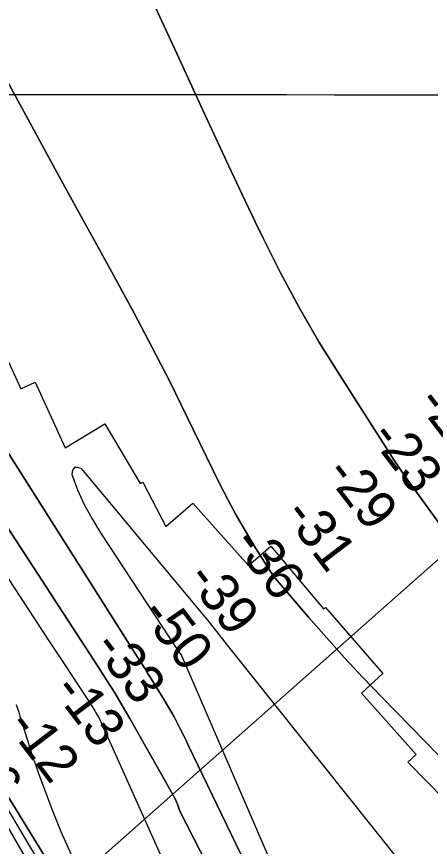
# Model space of a CAD drawing. Extents: x 3263578 to 3301413, y 764927 to 798602.
# Drawn here: x 3277420 to 3278134, y 786654 to 788086 of the extents above; entities that cross this region are included whole.
import ezdxf

# ---------------------------------------------------------------- set-up
doc = ezdxf.new("R2010")
doc.units = 0
for name, color, linetype in [('V-GRID-MAJR', 7, 'Continuous'), ('V-RIVR-RANG', 7, 'Continuous'), ('V-RRAP-RVMT', 7, 'Continuous'), ('V-TOPO-DPTH', 7, 'Continuous'), ('V-TOPO-MAJR', 7, 'Continuous'), ('V-TOPO-MINR', 7, 'Continuous'), ('V-TOPO-WATR', 7, 'Continuous')]:
    doc.layers.add(name, color=color, linetype=linetype)

msp = doc.modelspace()

# ---------------------------------------------------------------- linework, layer by layer
at = {"layer": 'V-GRID-MAJR'}
msp.add_spline([(3267732.7, 787953.5), (3270352.8, 787952.6), (3275593.1, 787951.5), (3280833.3, 787951.1), (3286073.6, 787951.5), (3291313.9, 787952.6), (3296554.1, 787954.5), (3299174.3, 787955.8)], degree=3, dxfattribs=at)
at = {"layer": 'V-RIVR-RANG'}
msp.add_line((3277254.1, 786359.2), (3278147.4, 787150), dxfattribs=at)
at = {"layer": 'V-RRAP-RVMT'}
for points in [[(3277050.8, 788201.5), (3277092.3, 788067.5), (3277100.3, 788070.3), (3277145.8, 787939.5), (3277153.8, 787942.5), (3277203.6, 787813.6), (3277212, 787817.1), (3277268.9, 787682.6), (3277302.2, 787696.7), (3277355.5, 787571), (3277366.6, 787576), (3277427.3, 787443.4), (3277452.4, 787454.9), (3277504, 787341.9)], [(3277504, 787341.9), (3277572.5, 787383.3), (3277633, 787280.3), (3277637.7, 787282.8), (3277677.4, 787206), (3277723.8, 787246.4), (3277819.9, 787138.6), (3277858.7, 787172.1), (3277949.5, 787063.9), (3277952.5, 787066.3), (3278051.7, 786952.4), (3278014.9, 786918.5), (3278108.9, 786812.7), (3278094.4, 786799.8), (3278190.5, 786701.7)]]:
    msp.add_lwpolyline(points, dxfattribs=at)
at = {"layer": 'V-TOPO-DPTH'}
for points in [[(3276856.5, 788146.6), (3276909.9, 787892.1), (3276910.3, 787890.2), (3276910.8, 787888.4), (3276911.4, 787886.6), (3276912.1, 787884.8), (3276912.9, 787883.1), (3276913.7, 787881.3), (3276914.7, 787879.7), (3276915.7, 787878), (3277398.4, 787128), (3277424.1, 787088.2), (3277449.9, 787048.4), (3277475.9, 787008.7), (3277502, 786969), (3277551.8, 786893.6), (3277553, 786891.7), (3277554.2, 786889.8), (3277555.4, 786887.9), (3277556.5, 786885.9), (3277563.1, 786874.5), (3278015.9, 785863.7)], [(3276856.5, 788146.6), (3276909.9, 787892.1), (3276910.3, 787890.2), (3276910.8, 787888.4), (3276911.4, 787886.6), (3276912.1, 787884.8), (3276912.9, 787883.1), (3276913.7, 787881.3), (3276914.7, 787879.7), (3276915.7, 787878), (3277398.4, 787128), (3277424.1, 787088.2), (3277449.9, 787048.4), (3277475.9, 787008.7), (3277502, 786969), (3277551.8, 786893.6), (3277553, 786891.7), (3277554.2, 786889.8), (3277555.4, 786887.9), (3277556.5, 786885.9), (3277563.1, 786874.5), (3278015.9, 785863.7)], [(3277651.6, 788119.4), (3277673.9, 788070.7), (3277696.2, 788022.1), (3277718.6, 787973.4), (3277741, 787924.7), (3277763.5, 787876.2), (3277786.2, 787827.6), (3277809.1, 787779.2), (3277832.1, 787730.9), (3277844.7, 787704.6), (3277875.3, 787643.8), (3277907.3, 787583.8), (3277941.5, 787525), (3277977.2, 787467), (3278071.9, 787319.3), (3278078.9, 787308.6), (3278086, 787298), (3278093.3, 787287.6), (3278100.7, 787277.2), (3278323.2, 786970.6)], [(3277651.6, 788119.4), (3277673.9, 788070.7), (3277696.2, 788022.1), (3277718.6, 787973.4), (3277741, 787924.7), (3277763.5, 787876.2), (3277786.2, 787827.6), (3277809.1, 787779.2), (3277832.1, 787730.9), (3277844.7, 787704.6), (3277875.3, 787643.8), (3277907.3, 787583.8), (3277941.5, 787525), (3277977.2, 787467), (3278071.9, 787319.3), (3278078.9, 787308.6), (3278086, 787298), (3278093.3, 787287.6), (3278100.7, 787277.2), (3278323.2, 786970.6)], [(3278565.3, 786383.6), (3278049.6, 786911.8), (3278017.3, 786945.5), (3277985.4, 786979.7), (3277954.3, 787014.5), (3277923.6, 787049.8), (3277869.3, 787113.2), (3277866.2, 787117.1), (3277863.1, 787121.1), (3277860.3, 787125.1), (3277857.5, 787129.3), (3277830, 787172.8), (3277814, 787199.1), (3277798.6, 787225.7), (3277784.1, 787252.7), (3277770.2, 787280.2), (3277714.5, 787394.9), (3277684.7, 787455.1), (3277654.2, 787515), (3277622.8, 787574.4), (3277590.8, 787633.5), (3277558.4, 787692.3), (3277526, 787751.2), (3277493.8, 787810.1), (3277461.6, 787869.1), (3277332.1, 788106.4)], [(3277332.1, 788106.4), (3277461.6, 787869.1), (3277493.8, 787810.1), (3277526, 787751.2), (3277558.4, 787692.3), (3277590.8, 787633.5), (3277622.8, 787574.4), (3277654.2, 787515), (3277684.7, 787455.1), (3277714.5, 787394.9), (3277770.2, 787280.2), (3277784.1, 787252.7), (3277798.6, 787225.7), (3277814, 787199.1), (3277830, 787172.8), (3277857.5, 787129.3), (3277860.3, 787125.1), (3277863.1, 787121.1), (3277866.2, 787117.1), (3277869.3, 787113.2), (3277923.6, 787049.8), (3277954.3, 787014.5), (3277985.4, 786979.7), (3278017.3, 786945.5), (3278049.6, 786911.8), (3278565.3, 786383.6)], [(3277116.8, 787789.3), (3277632.7, 786974.6), (3277637.1, 786967.5), (3277641.6, 786960.4), (3277646, 786953.2), (3277650.4, 786946.1), (3277674.4, 786907.3), (3277680.3, 786897.5), (3277686, 786887.6), (3277691.6, 786877.6), (3277696.9, 786867.5), (3277702.2, 786857.3), (3277707.3, 786847.1), (3277712.4, 786836.8), (3277717.4, 786826.5), (3277814.9, 786624)], [(3277814.9, 786624), (3277717.4, 786826.5), (3277712.4, 786836.8), (3277707.3, 786847.1), (3277702.2, 786857.3), (3277696.9, 786867.5), (3277691.6, 786877.6), (3277686, 786887.6), (3277680.3, 786897.5), (3277674.4, 786907.3), (3277650.4, 786946.1), (3277646, 786953.2), (3277641.6, 786960.4), (3277637.1, 786967.5), (3277632.7, 786974.6), (3277116.8, 787789.3)], [(3278079.8, 785976.6), (3277701.7, 786714.9), (3277697.4, 786726.9), (3277692.2, 786738.5), (3277615.2, 786875), (3277602.5, 786897.1), (3277589.4, 786918.9), (3277576, 786940.5), (3277562.3, 786962), (3277312.5, 787345.4)], [(3278079.8, 785976.6), (3277701.7, 786714.9), (3277697.4, 786726.9), (3277692.2, 786738.5), (3277615.2, 786875), (3277602.5, 786897.1), (3277589.4, 786918.9), (3277576, 786940.5), (3277562.3, 786962), (3277312.5, 787345.4)], [(3277259.6, 786938), (3277928.1, 785781.1)], [(3277259.6, 786938), (3277928.1, 785781.1)], [(3277967.8, 785823.8), (3277388.8, 786766.2)], [(3277967.8, 785823.8), (3277388.8, 786766.2)]]:
    msp.add_lwpolyline(points, dxfattribs=at)
at = {"layer": 'V-TOPO-MAJR'}
msp.add_lwpolyline([(3278071.7, 786640), (3277786.3, 786998.7), (3277769.4, 787019.8), (3277752.5, 787040.8), (3277735.4, 787061.6), (3277718.2, 787082.4), (3277532.7, 787305.4), (3277525.5, 787308.1), (3277519.9, 787307.8), (3277516.8, 787303.1), (3277515.3, 787295.6), (3277525.5, 787269.5), (3277537, 787244), (3277550.3, 787219.5), (3277564.8, 787195.5), (3277684.1, 787013.8), (3277689.1, 787006.2), (3277694.2, 786998.5), (3277699.3, 786990.9), (3277704.4, 786983.3), (3278016.2, 786261.8)], dxfattribs=at)
at = {"layer": 'V-TOPO-MINR'}
for points in [[(3276856.5, 788146.6), (3276909.9, 787892.1), (3276910.3, 787890.2), (3276910.8, 787888.4), (3276911.4, 787886.6), (3276912.1, 787884.8), (3276912.9, 787883.1), (3276913.7, 787881.3), (3276914.7, 787879.7), (3276915.7, 787878), (3277398.4, 787128), (3277424.1, 787088.2), (3277449.9, 787048.4), (3277475.9, 787008.7), (3277502, 786969), (3277551.8, 786893.6), (3277553, 786891.7), (3277554.2, 786889.8), (3277555.4, 786887.9), (3277556.5, 786885.9), (3277563.1, 786874.5), (3278015.9, 785863.7)], [(3278323.2, 786970.6), (3278100.7, 787277.2), (3278093.3, 787287.6), (3278086, 787298), (3278078.9, 787308.6), (3278071.9, 787319.3), (3277977.2, 787467), (3277941.5, 787525), (3277907.3, 787583.8), (3277875.3, 787643.8), (3277844.7, 787704.6), (3277832.1, 787730.9), (3277809.1, 787779.2), (3277786.2, 787827.6), (3277763.5, 787876.2), (3277741, 787924.7), (3277718.6, 787973.4), (3277696.2, 788022.1), (3277673.9, 788070.7), (3277651.6, 788119.4)], [(3278565.3, 786383.6), (3278049.6, 786911.8), (3278017.3, 786945.5), (3277985.4, 786979.7), (3277954.3, 787014.5), (3277923.6, 787049.8), (3277869.3, 787113.2), (3277866.2, 787117.1), (3277863.1, 787121.1), (3277860.3, 787125.1), (3277857.5, 787129.3), (3277830, 787172.8), (3277814, 787199.1), (3277798.6, 787225.7), (3277784.1, 787252.7), (3277770.2, 787280.2), (3277714.5, 787394.9), (3277684.7, 787455.1), (3277654.2, 787515), (3277622.8, 787574.4), (3277590.8, 787633.5), (3277558.4, 787692.3), (3277526, 787751.2), (3277493.8, 787810.1), (3277461.6, 787869.1), (3277332.1, 788106.4)], [(3277116.8, 787789.3), (3277632.7, 786974.6), (3277637.1, 786967.5), (3277641.6, 786960.4), (3277646, 786953.2), (3277650.4, 786946.1), (3277674.4, 786907.3), (3277680.3, 786897.5), (3277686, 786887.6), (3277691.6, 786877.6), (3277696.9, 786867.5), (3277702.2, 786857.3), (3277707.3, 786847.1), (3277712.4, 786836.8), (3277717.4, 786826.5), (3277814.9, 786624)], [(3277312.5, 787345.4), (3277562.3, 786962), (3277576, 786940.5), (3277589.4, 786918.9), (3277602.5, 786897.1), (3277615.2, 786875), (3277692.2, 786738.5), (3277697.4, 786726.9), (3277701.7, 786714.9), (3278079.8, 785976.6)], [(3277419.7, 786898.8), (3277421.8, 786892.2), (3277423.9, 786885.6), (3277425.9, 786879), (3277438.8, 786837.3), (3277443.2, 786823.4), (3277447.8, 786809.5), (3277452.6, 786795.7), (3277457.5, 786781.9), (3277480.2, 786720.4), (3277496.6, 786679.9), (3277514.6, 786640.2)], [(3277379.2, 786760.2), (3277947.9, 785802.4)], [(3277388.8, 786766.2), (3277967.8, 785823.8)]]:
    msp.add_lwpolyline(points, dxfattribs=at)
at = {"layer": 'V-TOPO-WATR'}
msp.add_lwpolyline([(3277259.6, 786938), (3277928.1, 785781.1)], dxfattribs=at)

# ---------------------------------------------------------------- texts
at = {"layer": 'V-RIVR-RANG'}
for s, p in [('-20', (3278108.5, 787419.5)), ('-23', (3278027.5, 787360.8)), ('-29', (3277950.1, 787297.4)), ('-31', (3277878.6, 787226.3)), ('-36', (3277790.6, 787176.8)), ('-39', (3277711.2, 787116)), ('-50', (3277632, 787055)), ('-33', (3277550, 786997.5)), ('-13', (3277481.1, 786923)), ('-12', (3277401.9, 786862)), ('-6', (3277333.2, 786787.1))]:
    msp.add_text(s, height=67, rotation=307.3775, dxfattribs=at).set_placement(p)

doc.saveas('drawing.dxf')
